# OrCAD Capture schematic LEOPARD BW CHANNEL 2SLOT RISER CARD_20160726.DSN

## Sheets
1 008 HISTORY: title: 008 HISTORY; rev: SA; company: Wiwynn Corporation; note: LEOPARD BW CHANNEL RISER CARD; note: 8F, No.90, Xintai 5th Rd., Xizhi Dist,; note: New Taipei, Taiwan
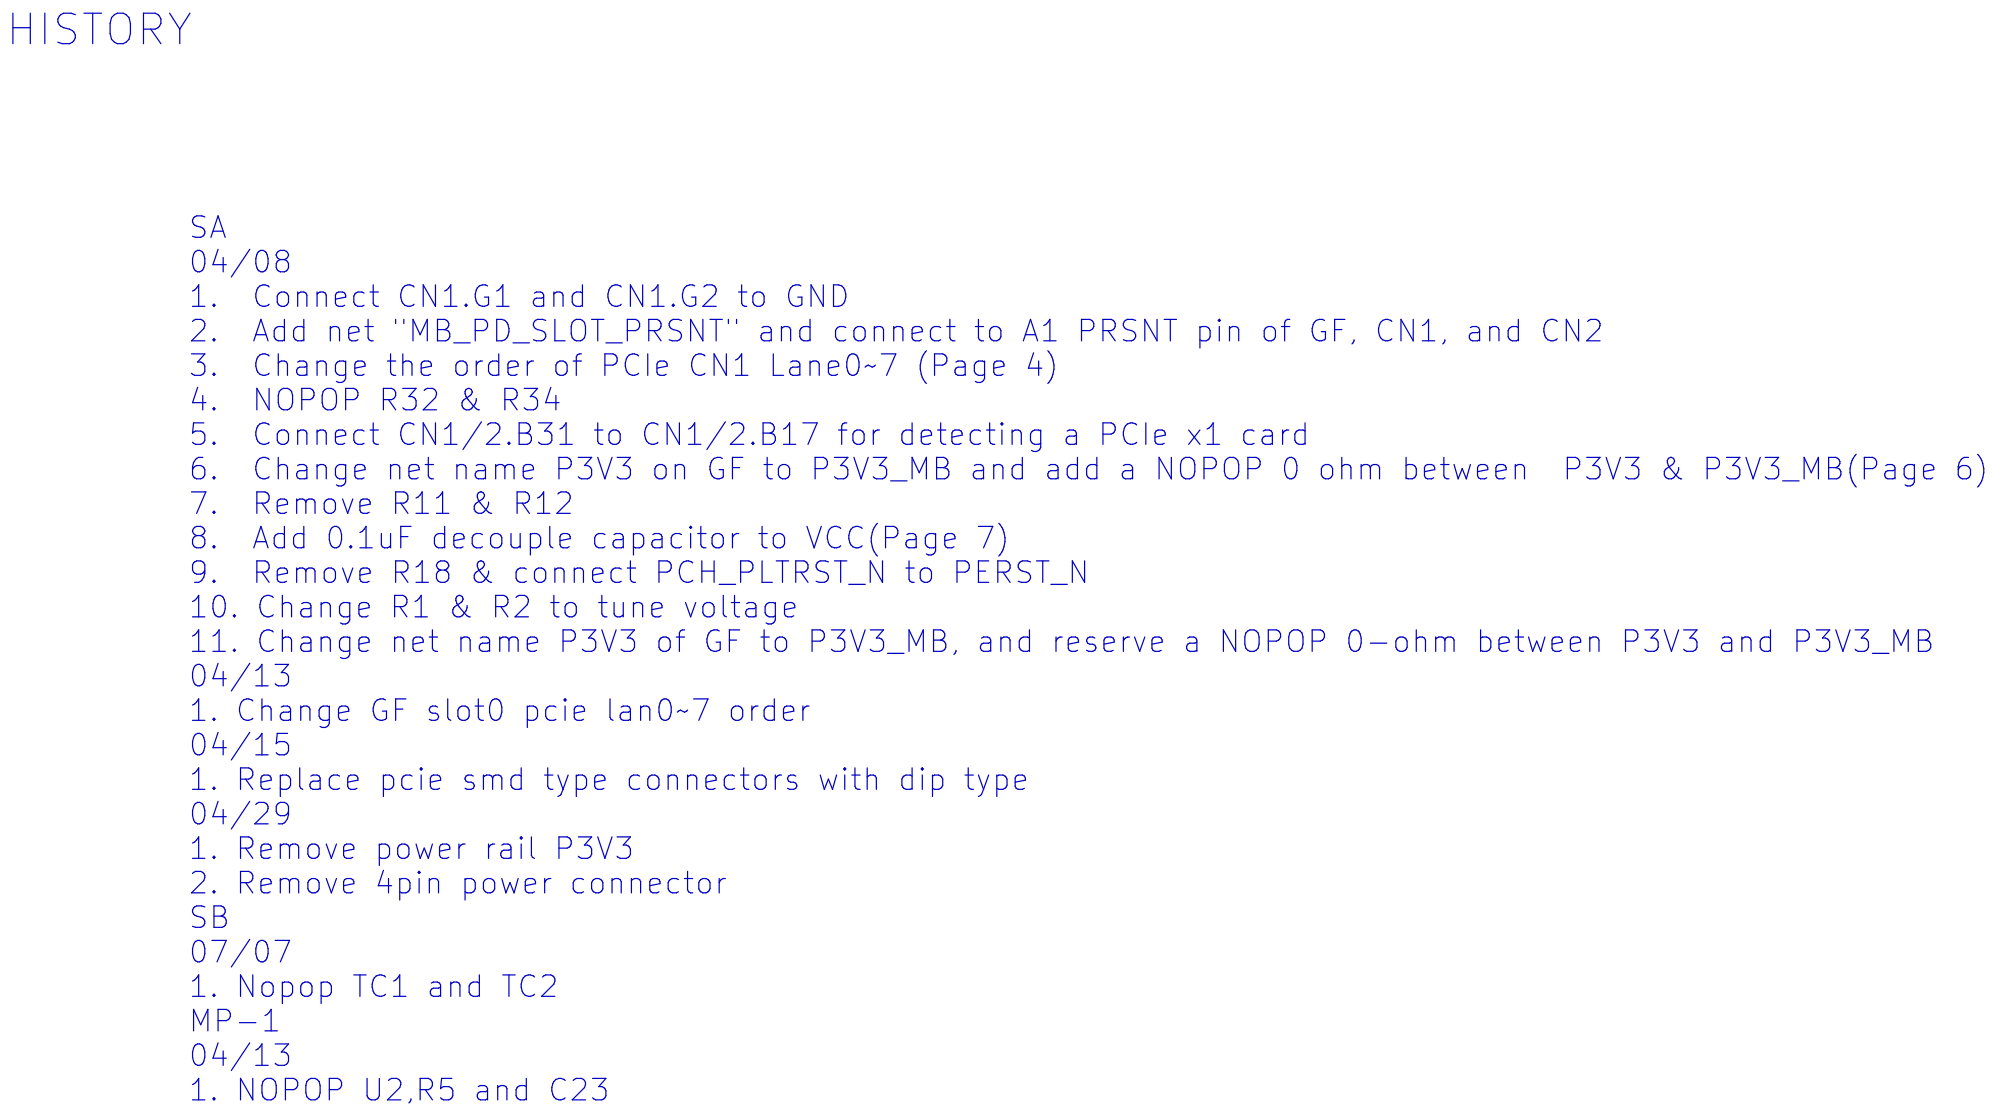
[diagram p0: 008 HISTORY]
2 007 I2C-Bus Multiplexer: size A4; title: 007 I2C-Bus Multiplexer
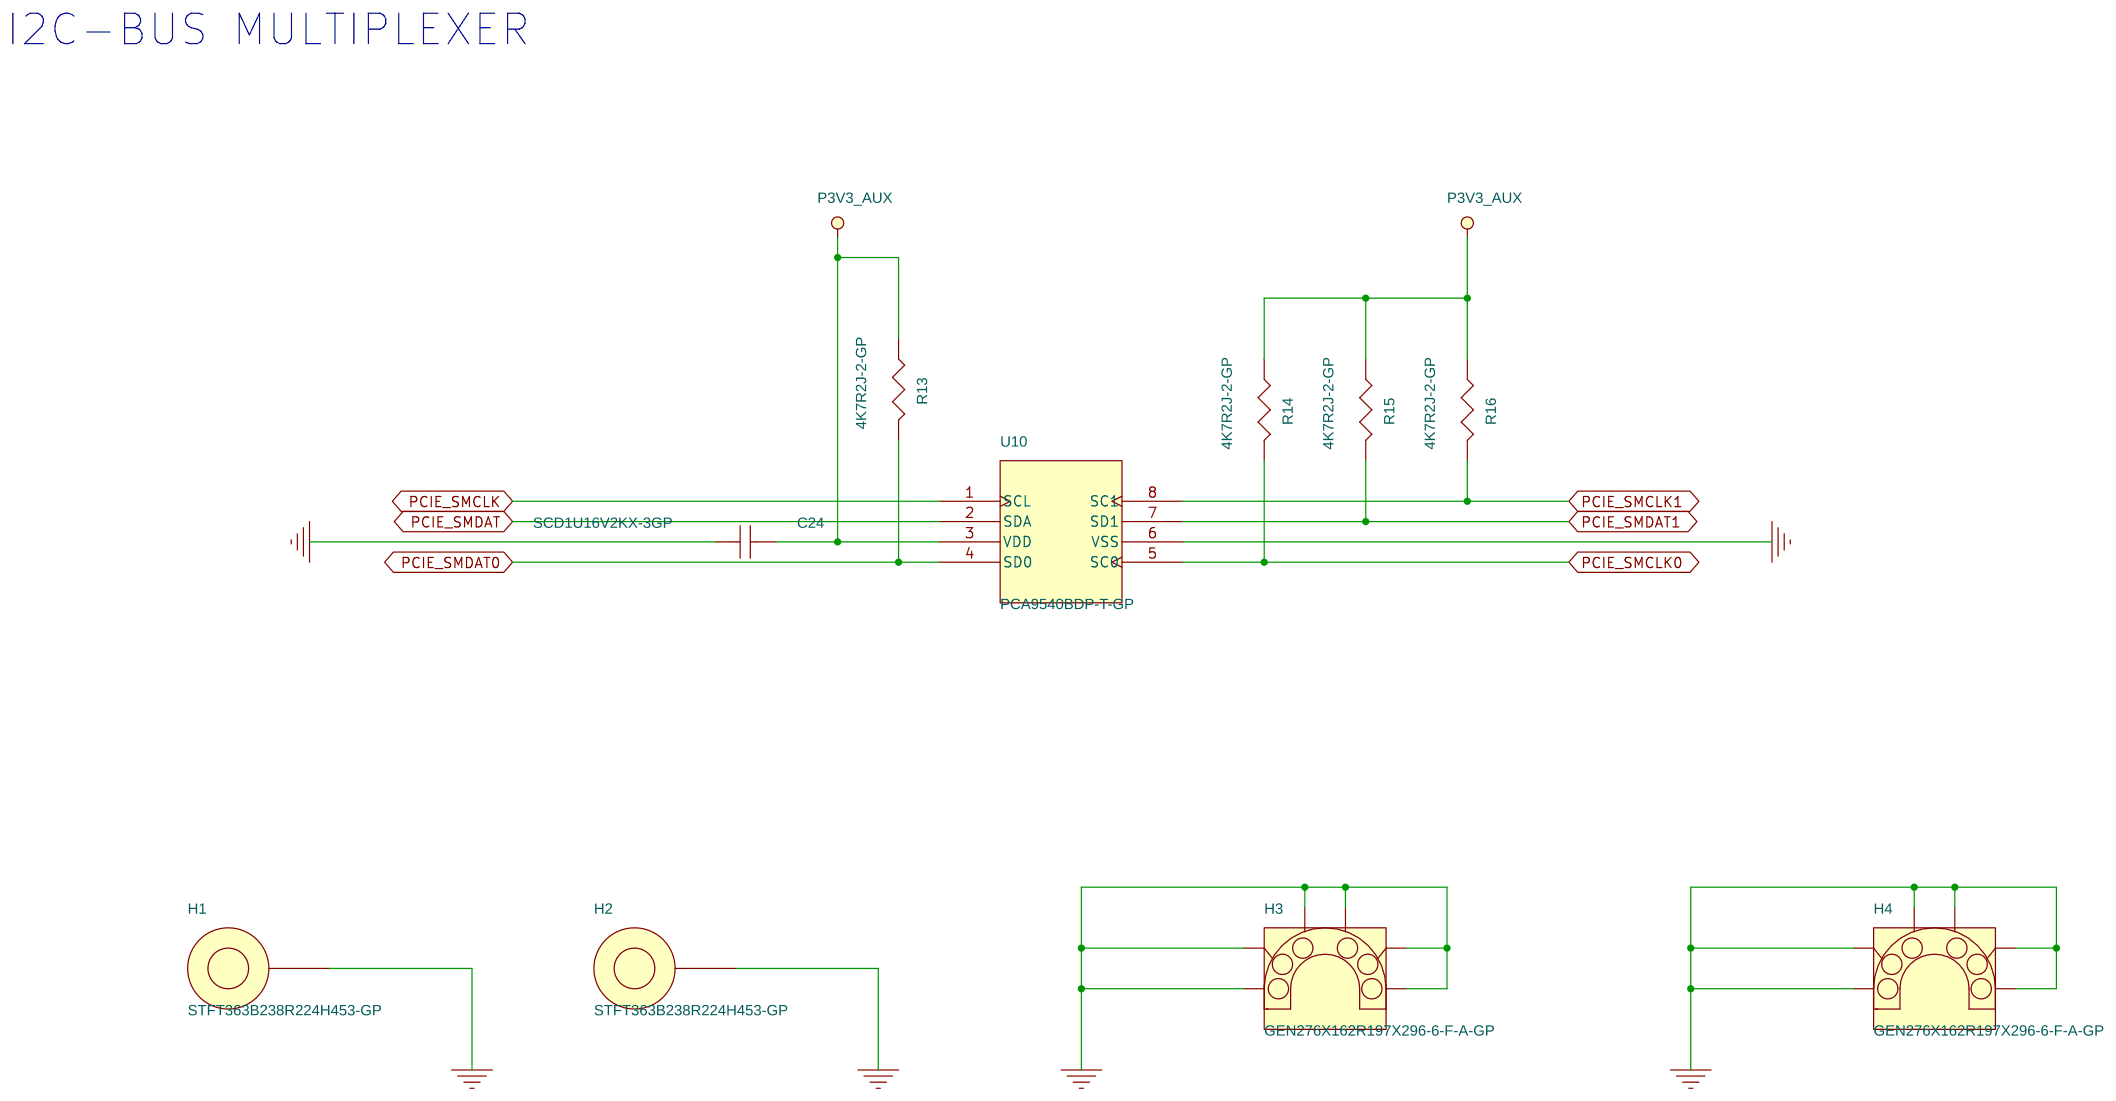
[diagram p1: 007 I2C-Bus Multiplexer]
3 006 PCIE X24 RISER GF: size A2; title: 006 PCIE X24 RISER GF
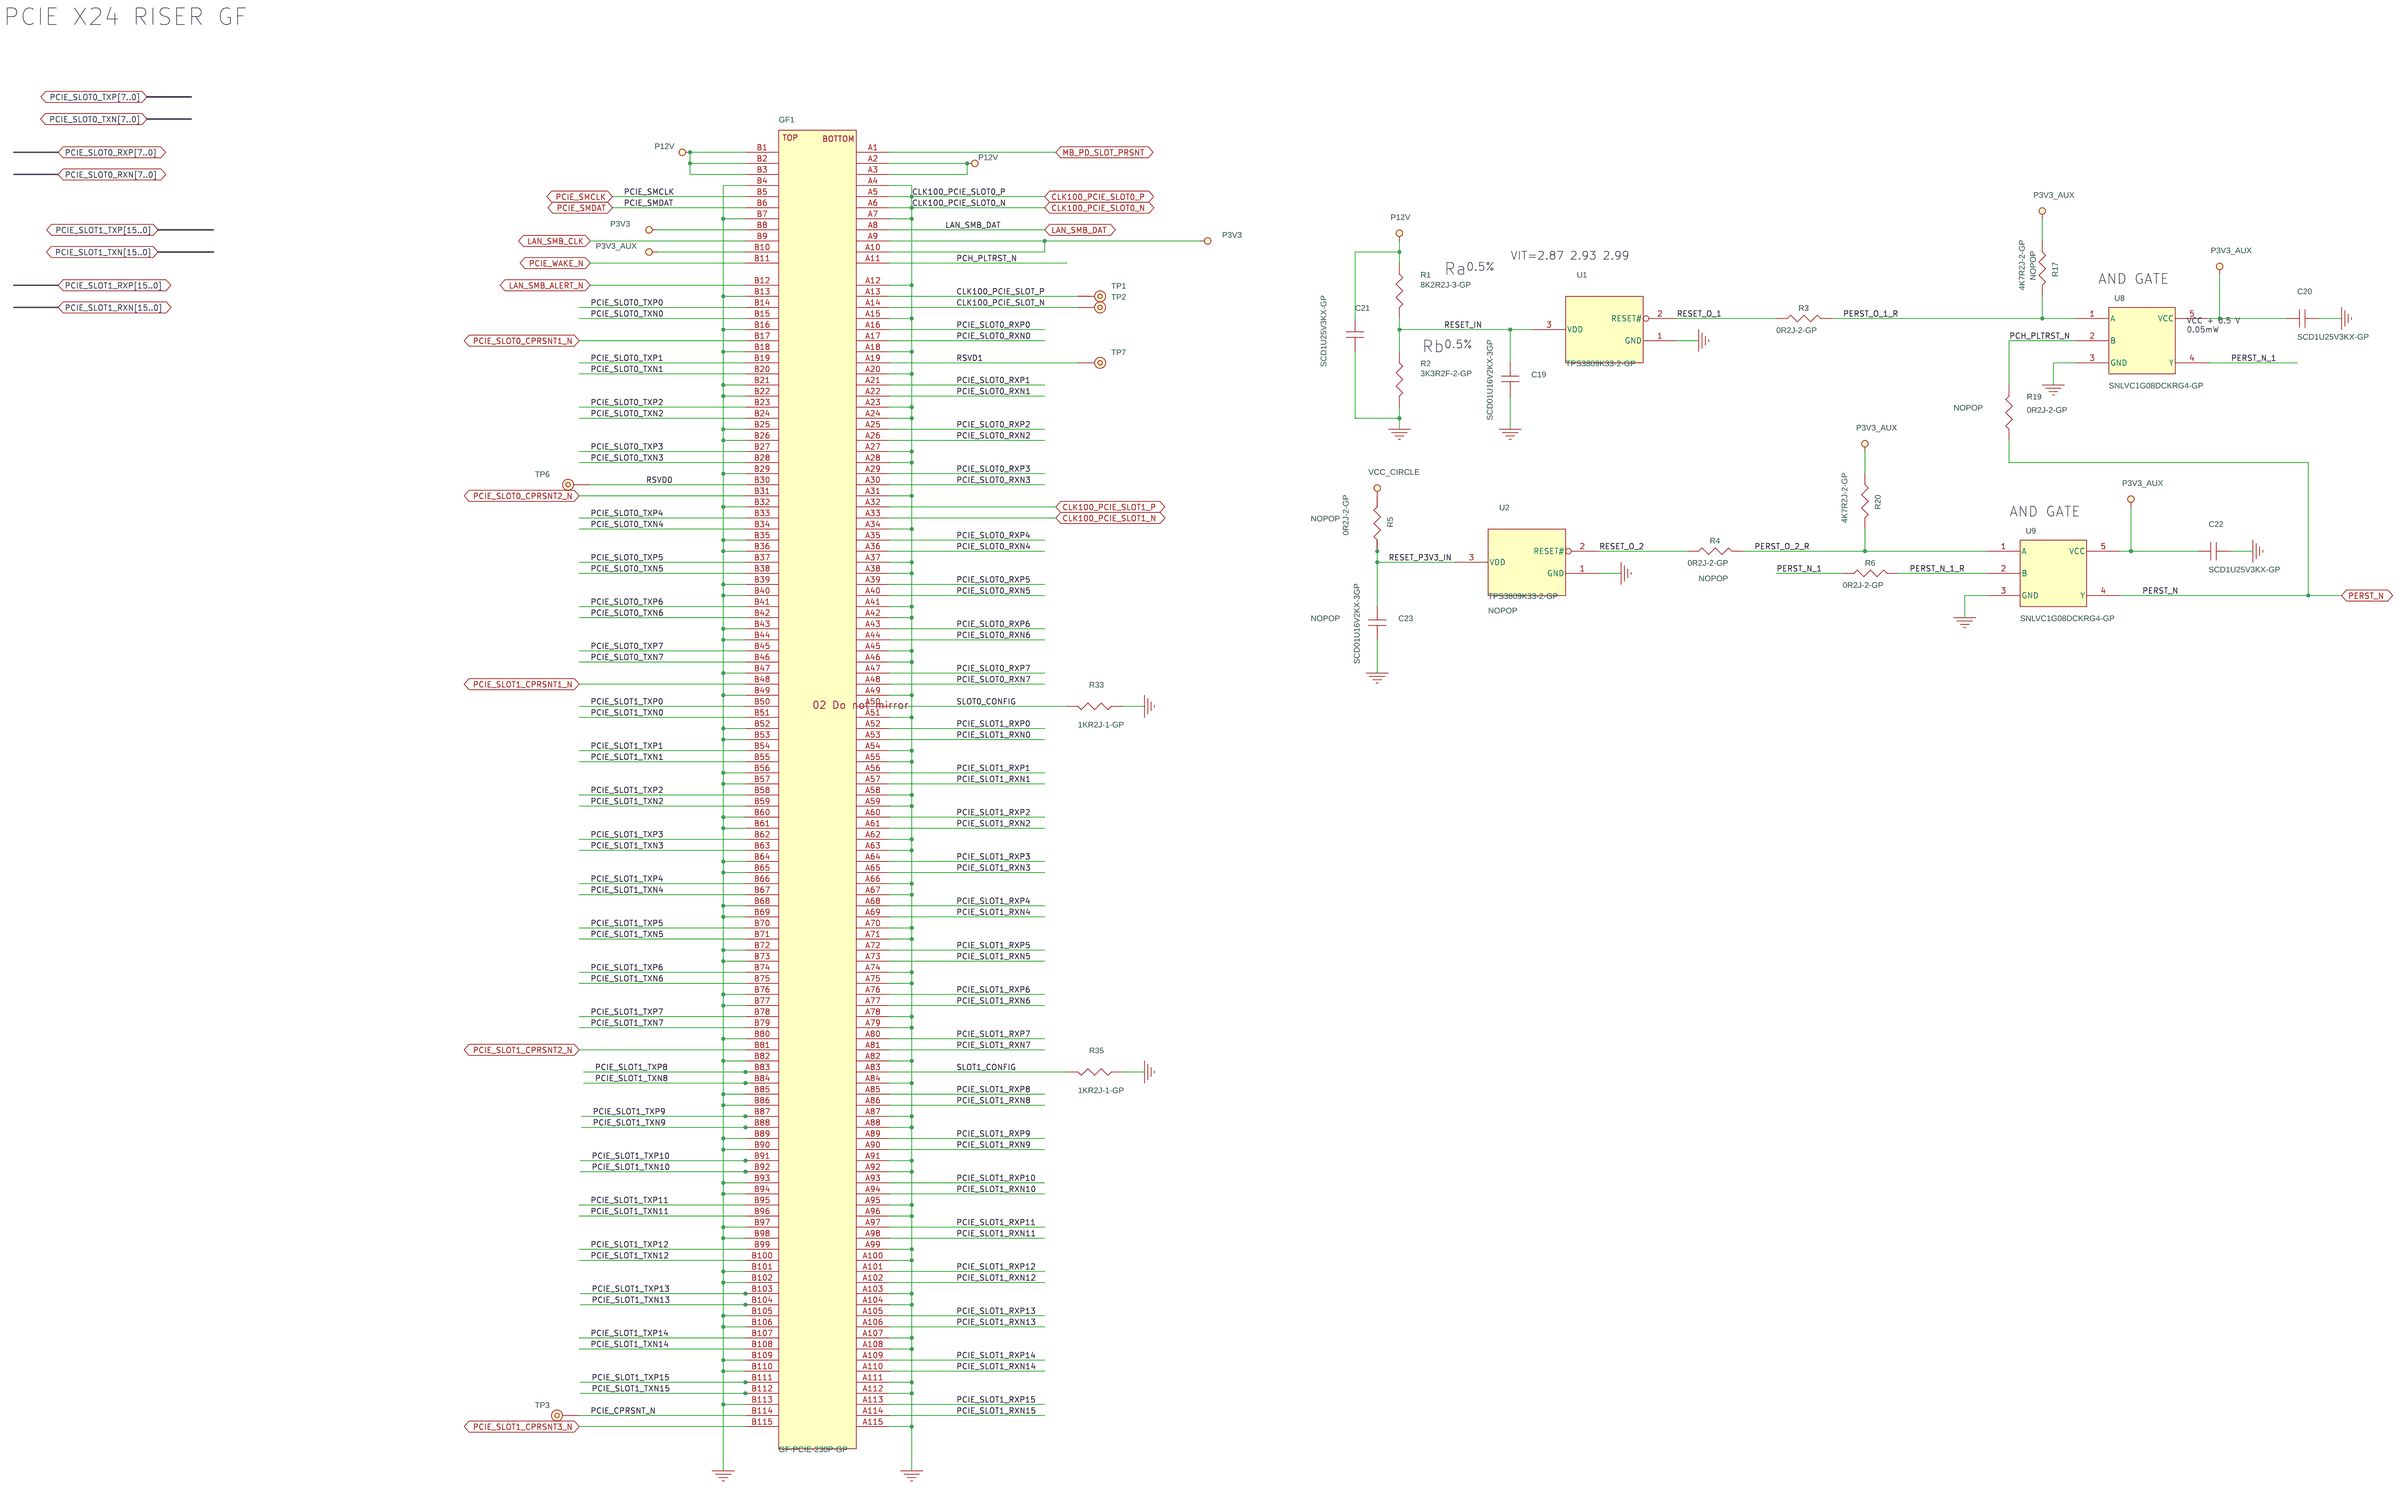
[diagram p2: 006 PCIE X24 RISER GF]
4 005 PCIE X16 RISER SLOT2: size A3; title: 005 PCIE X16 RISER SLOT3
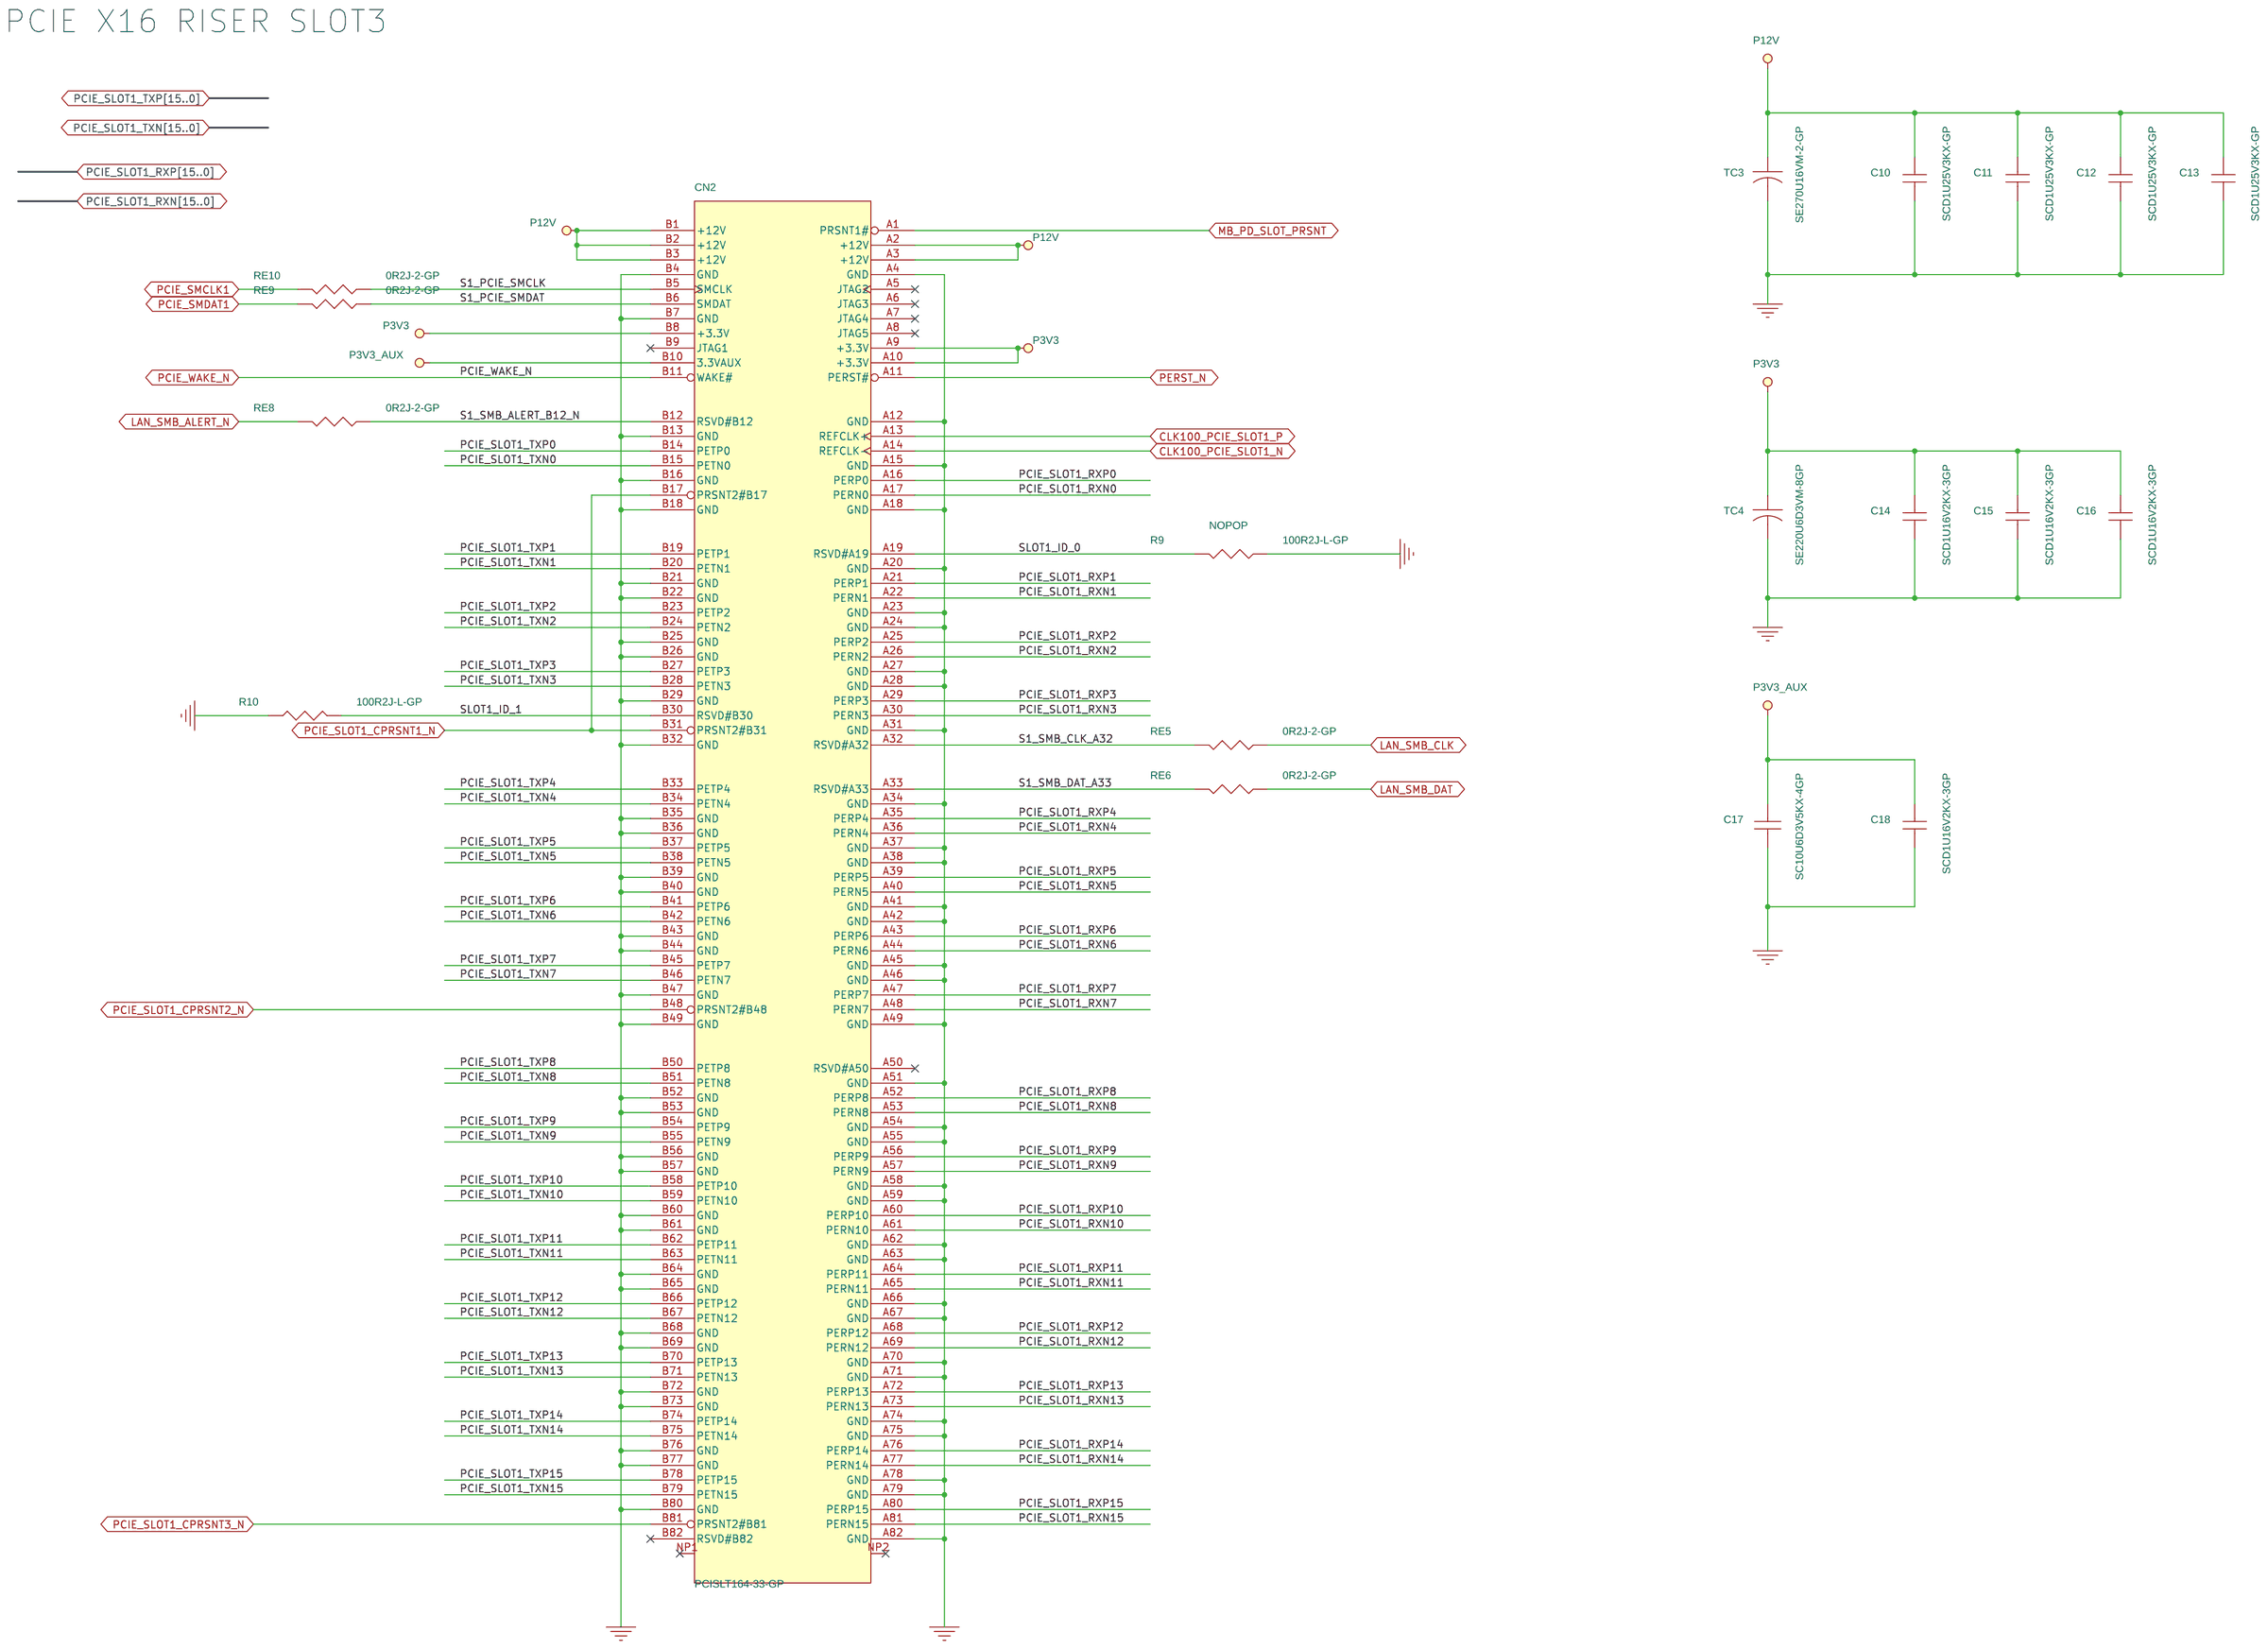
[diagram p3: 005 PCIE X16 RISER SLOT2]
5 004 PCIE X8 RISER SLOT1: size A3; title: 004 PCIE X8 RISER SLOT2
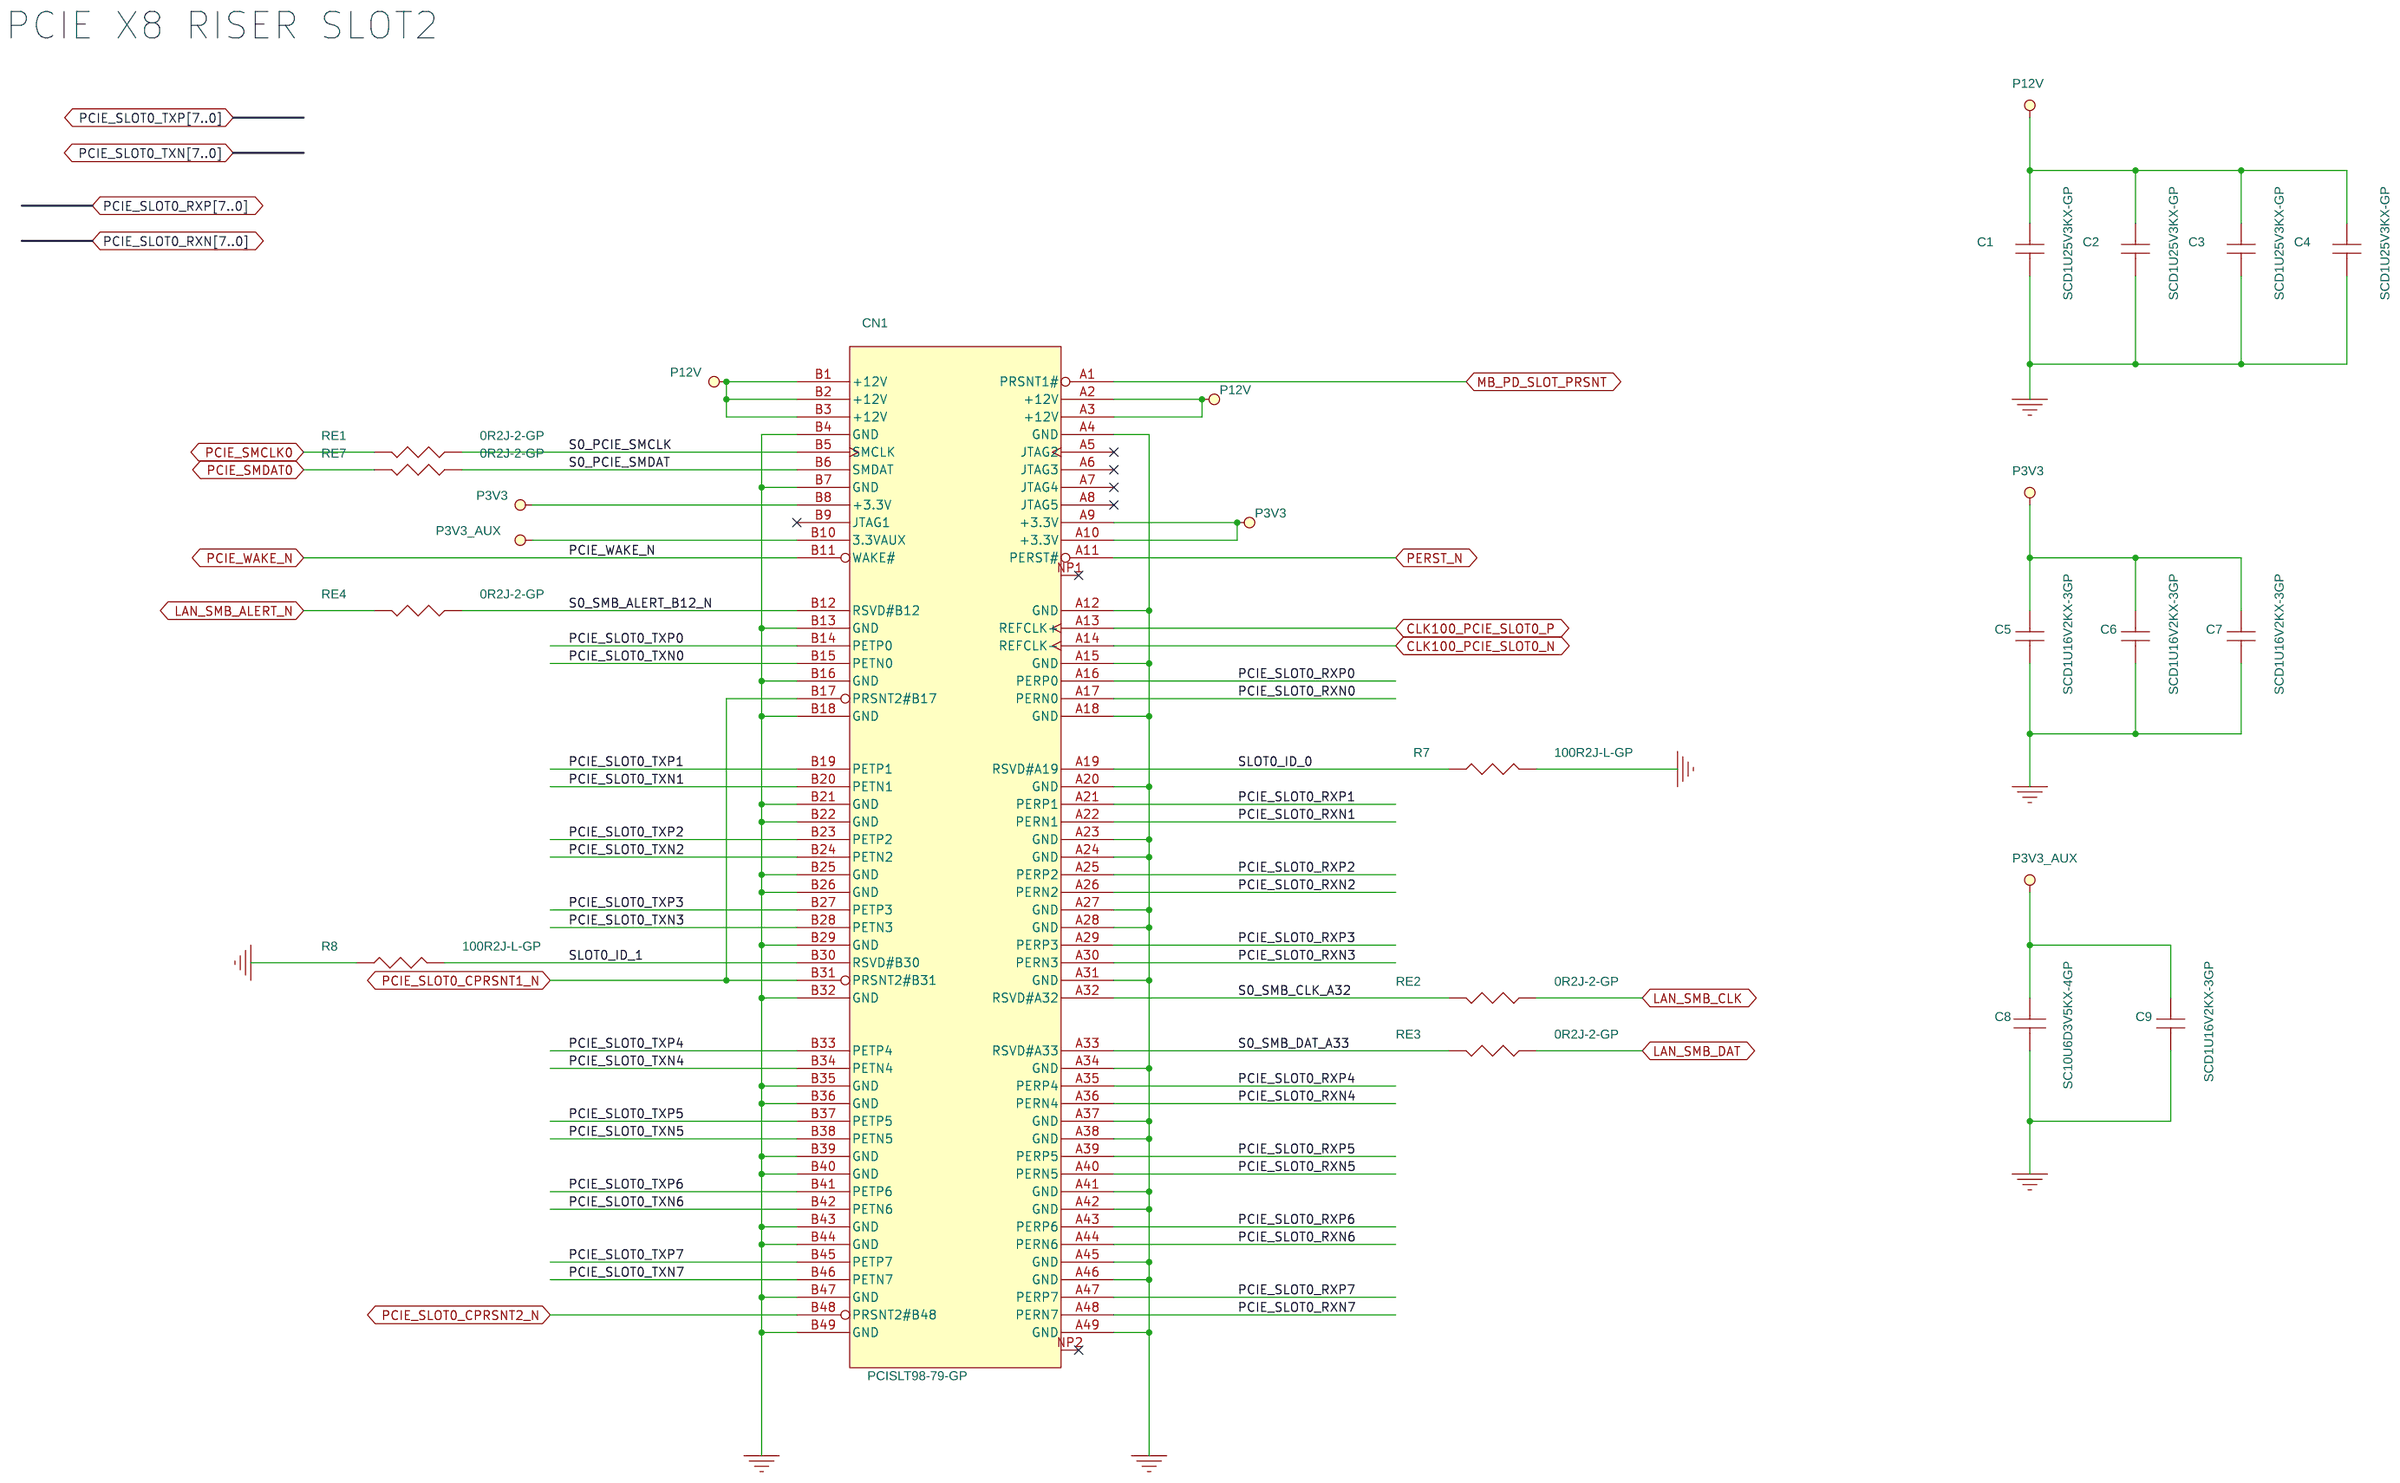
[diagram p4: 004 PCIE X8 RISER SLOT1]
6 003 STACKUP: title: 003 STACKUP
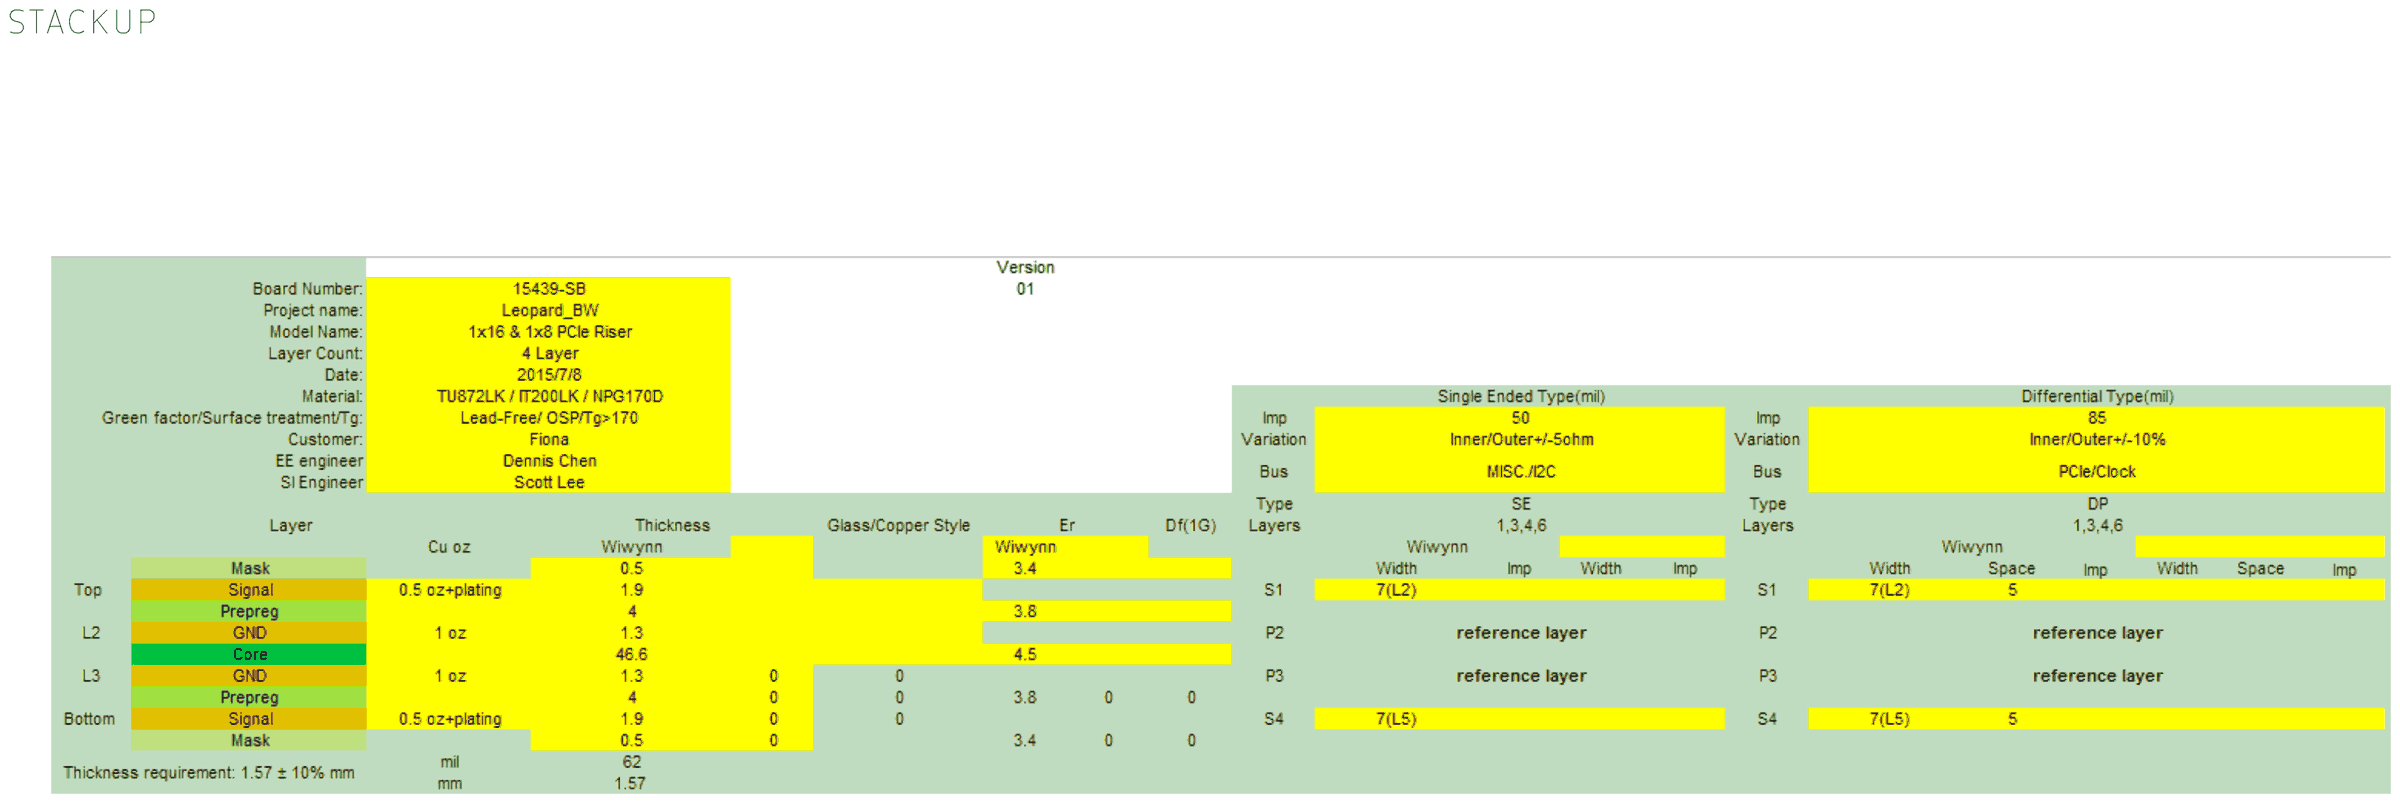
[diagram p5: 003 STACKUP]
7 002 BLOCK DIAGRAM: title: 002 BLOCK DIAGRAM
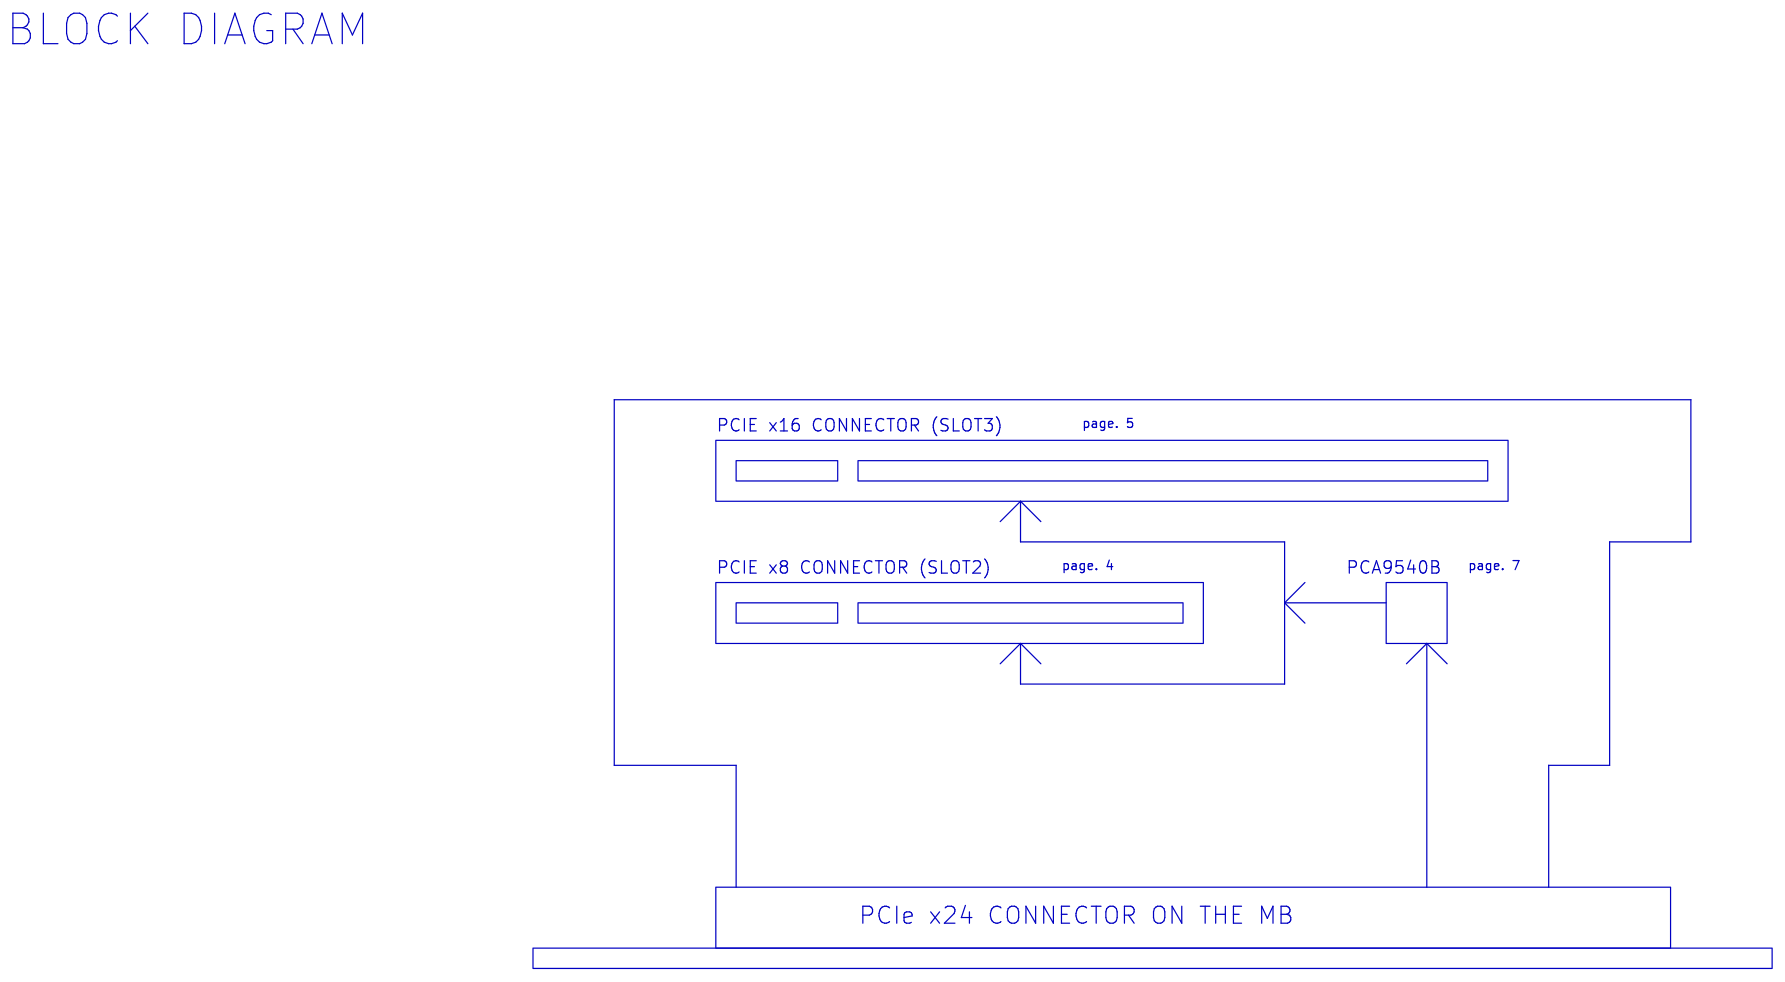
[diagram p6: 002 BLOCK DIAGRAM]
8 001 COVER PAGE: title: 001 COVER PAGE
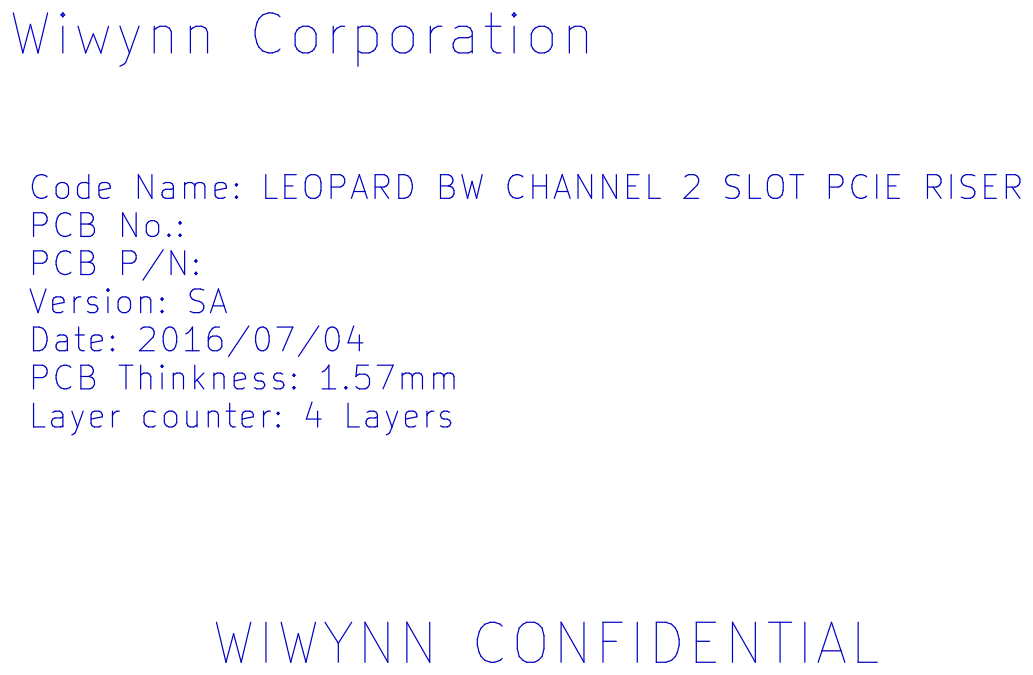
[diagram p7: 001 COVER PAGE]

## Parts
sheet 004 PCIE X8 RISER SLOT1
C1  SCD1U25V3KX-GP  [C603H36]
C2  SCD1U25V3KX-GP  [C603H36]
C3  SCD1U25V3KX-GP  [C603H36]
C4  SCD1U25V3KX-GP  [C603H36]
C5  SCD1U16V2KX-3GP  [C402H22]
C6  SCD1U16V2KX-3GP  [C402H22]
C7  SCD1U16V2KX-3GP  [C402H22]
C8  SC10U6D3V5KX-4GP  [C805H58]
C9  SCD1U16V2KX-3GP  [C402H22]
CN1  PCISLT98-79-GP  [G630H9811210TEU]
R7  100R2J-L-GP  [R402H15]
R8  100R2J-L-GP  [R402H15]
RE1  0R2J-2-GP  [R402H16]
RE2  0R2J-2-GP  [R402H16]
RE3  0R2J-2-GP  [R402H16]
RE4  0R2J-2-GP  [R402H16]
RE7  0R2J-2-GP  [R402H16]
sheet 005 PCIE X16 RISER SLOT2
C10  SCD1U25V3KX-GP  [C603H36]
C11  SCD1U25V3KX-GP  [C603H36]
C12  SCD1U25V3KX-GP  [C603H36]
C13  SCD1U25V3KX-GP  [C603H36]
C14  SCD1U16V2KX-3GP  [C402H22]
C15  SCD1U16V2KX-3GP  [C402H22]
C16  SCD1U16V2KX-3GP  [C402H22]
C17  SC10U6D3V5KX-4GP  [C805H58]
C18  SCD1U16V2KX-3GP  [C402H22]
CN2  PCISLT164-33-GP  [2EG08227-D2W-DF]
R9  100R2J-L-GP  [R402H15]
R10  100R2J-L-GP  [R402H15]
RE5  0R2J-2-GP  [R402H16]
RE6  0R2J-2-GP  [R402H16]
RE8  0R2J-2-GP  [R402H16]
RE9  0R2J-2-GP  [R402H16]
RE10  0R2J-2-GP  [R402H16]
TC3  SE270U16VM-2-GP  [SE391427H276]
TC4  SE220U6D3VM-8GP  [SE331721H237]
sheet 006 PCIE X24 RISER GF
C19  SCD01U16V2KX-3GP  [C402H22]
C20  SCD1U25V3KX-GP  [C603H36]
C21  SCD1U25V3KX-GP  [C603H36]
C22  SCD1U25V3KX-GP  [C603H36]
C23  SCD01U16V2KX-3GP  [C402H22]
GF1  GF-PCIE-230P-GP  [GF-PCIE-230P]
R1  8K2R2J-3-GP  [R402H16]
R2  3K3R2F-2-GP  [R402H16]
R3  0R2J-2-GP  [R402H16]
R4  0R2J-2-GP  [R402H16]
R5  0R2J-2-GP  [R402H16]
R6  0R2J-2-GP  [R402H16]
R17  4K7R2J-2-GP  [R402H16]
R19  0R2J-2-GP  [R402H16]
R20  4K7R2J-2-GP  [R402H16]
R33  1KR2J-1-GP  [R402H16]
R35  1KR2J-1-GP  [R402H16]
TP1  TPAD24  [TPAD24]
TP2  TPAD24  [TPAD24]
TP3  TPAD24  [TPAD24]
TP6  TPAD24  [TPAD24]
TP7  TPAD24  [TPAD24]
U1  TPS3809K33-2-GP  [SOT-23-1H58]
U2  TPS3809K33-2-GP  [SOT-23-1H58]
U8  SNLVC1G08DCKRG4-GP  [SC70-5H44]
U9  SNLVC1G08DCKRG4-GP  [SC70-5H44]
sheet 007 I2C-Bus Multiplexer
C24  SCD1U16V2KX-3GP  [C402H22]
H1  STFT363B238R224H453-GP  [STFT363B238R224H453]
H2  STFT363B238R224H453-GP  [STFT363B238R224H453]
H3  GEN276X162R197X296-6-F-A-GP  [GEN276X162R197X296-6-F-A]
H4  GEN276X162R197X296-6-F-A-GP  [GEN276X162R197X296-6-F-A]
R13  4K7R2J-2-GP  [R402H16]
R14  4K7R2J-2-GP  [R402H16]
R15  4K7R2J-2-GP  [R402H16]
R16  4K7R2J-2-GP  [R402H16]
U10  PCA9540BDP-T-GP  [SSOIC8-2H44]

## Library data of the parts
C1-C4 C10-C13 = SCD1U25V3KX-GP: CHIP CAP C 0.1U 25V K0603 X7R; CATEGORIES: CAP_1.xV; GREENDFACTOR: R2_SA;HF_SA;G_SA;; MAIN_SOURCE: M; Part Number: 78.10422.2BL; Part Type: RCL_GP; SPEC: http://wpqssvr.wistron.com.tw:7001/wpqs/servlet/COM.qpart.Attachment?PartNumber=78.10422.2BL
C5-C7 C9 C14-C16 C18 = SCD1U16V2KX-3GP: CHIP CAP C 0.1U 16V K0402 X7R; CATEGORIES: CAP_1.xV; GREENDFACTOR: R2_SA;HF_SA;G_SA;; MAIN_SOURCE: M; POP?: POP; Package Type: SMD-BCG; Part Number: 78.10421.2FL; SPEC: http://wpqssvr.wistron.com.tw:7001/wpqs/servlet/COM.qpart.Attachment?PartNumber=78.10421.2FL
C8 C17 = SC10U6D3V5KX-4GP: CHIP CAP C 10U 6.3V K0805 X7R; GREENDFACTOR: R2_SA;HF_SA;G_SA;; POP?: POP; Package Type: SMD-BCG; Part Number: 78.10620.21L; SPEC: http://wpqssvr.wistron.com.tw:7001/wpqs/servlet/COM.qpart.Attachment?PartNumber=78.10620.21L
CN1 = PCISLT98-79-GP: CONN EDGE DIP 98P G630H9811210TEU; GREENDFACTOR: R2_C;; Part Number: 020.50107.0098; Part Type: CONN-G7; SPEC: http://wpqssvr.wistron.com.tw:7001/wpqs/servlet/COM.qpart.Attachment?PartNumber=020.50107.0098
R7 R8 R10 = 100R2J-L-GP: CHIP RES 100 J 1/16W 0402 13" REEL; GREENDFACTOR: R2_SA;HF_SA;G_SA;; POP?: POP; Package Type: SMD-RG5; Part Number: 63.10134.L0L; SPEC: http://wpqssvr.wistron.com.tw:7001/wpqs/servlet/COM.qpart.Attachment?PartNumber=63.10134.L0L
RE1-RE10 = 0R2J-2-GP: CHIP RES 0 J 1/16W 0402; Category: CPLD; GREENDFACTOR: R2_SA;HF_SA;G_SA;; POP?: POP; Part Number: 63.R0034.1DL; Part Type: SMD-RG; SPEC: http://wpqssvr.wistron.com.tw:7001/wpqs/servlet/COM.qpart.Attachment?PartNumber=63.R0034.1DL
CN2 = PCISLT164-33-GP: CONN EDGE 164P ST 1-1734774-6 ,PA46/PA9T; GREENDFACTOR: R2_SA;HF_SA;; Part Number: 20.50449.164; Part Type: CONN-G6; SPEC: http://wpqssvr.wistron.com.tw:7001/wpqs/servlet/COM.qpart.Attachment?PartNumber=20.50449.164
R9 = 100R2J-L-GP: CHIP RES 100 J 1/16W 0402 13" REEL; GREENDFACTOR: R2_SA;HF_SA;G_SA;; POP?: NOPOP; Package Type: SMD-RG5; Part Number: 63.10134.L0L; SPEC: http://wpqssvr.wistron.com.tw:7001/wpqs/servlet/COM.qpart.Attachment?PartNumber=63.10134.L0L
TC3 = SE270U16VM-2-GP: CHIP CAP 270U 16V M 8.0*6.9 SVPF OS-CON; GREENDFACTOR: R2_C;; Package Type: SMD-TCG1; Part Number: 77.52771.01L; SPEC: http://wpqssvr.wistron.com.tw:7001/wpqs/servlet/COM.qpart.Attachment?PartNumber=77.52771.01L
TC4 = SE220U6D3VM-8GP: CHIP CAP EL 220U6.3V M6.3*5.9; CATEGORIES: CAP_USB; GREENDFACTOR: R2_SA;HF_SA;; MAIN_SOURCE: M; Package Type: SMD-TCG; Part Number: 79.22710.E0L; SPEC: http://wpqssvr.wistron.com.tw:7001/wpqs/servlet/COM.qpart.Attachment?PartNumber=79.22710.E0L
C19 = SCD01U16V2KX-3GP: CHIP CAP C 0.01U 16V K0402 X7R; CATEGORIES: CAP_3V/5V; GREENDFACTOR: R2_SA;HF_SA;G_SA;; MAIN_SOURCE: M; Part Number: 78.10321.2FL; Part Type: SMD-BCG; SPEC: http://wpqssvr.wistron.com.tw:7001/wpqs/servlet/COM.qpart.Attachment?PartNumber=78.10321.2FL
C20 C22 = SCD1U25V3KX-GP: CHIP CAP C 0.1U 25V K0603 X7R; CATEGORIES: CAP_1.xV; GREENDFACTOR: R2_SA;R_SA;HF_SA;G_SA;; MAIN_SOURCE: M; POP?: POP; Package Type: RCL_GP; Part Number: 78.10422.2BL; SPEC: http://wpqssvr.wistron.com.tw:7001/wpqs/servlet/COM.qpart.Attachment?PartNumber=78.10422.2BL
C21 = SCD1U25V3KX-GP: CHIP CAP C 0.1U 25V K0603 X7R; CATEGORIES: CAP_1.xV; GREENDFACTOR: R2_SA;HF_SA;G_SA;; MAIN_SOURCE: M; POP?: POP; Package Type: RCL_GP; Part Number: 78.10422.2BL; SPEC: http://wpqssvr.wistron.com.tw:7001/wpqs/servlet/COM.qpart.Attachment?PartNumber=78.10422.2BL
C23 = SCD01U16V2KX-3GP: CHIP CAP C 0.01U 16V K0402 X7R; CATEGORIES: CAP_3V/5V; GREENDFACTOR: R2_SA;HF_SA;G_SA;; MAIN_SOURCE: M; POP?: NOPOP; Part Number: 78.10321.2FL; Part Type: SMD-BCG; SPEC: http://wpqssvr.wistron.com.tw:7001/wpqs/servlet/COM.qpart.Attachment?PartNumber=78.10321.2FL
GF1 = GF-PCIE-230P-GP: PCIE GOLD FINGURE 230P; GREENDFACTOR: R2_C;; Package Type: CONN-G7; Part Number: ZZ.GF001.711; SPEC: http://wpqssvr.wistron.com.tw:7001/wpqs/servlet/COM.qpart.Attachment?PartNumber=ZZ.GF001.711
R1 = 8K2R2J-3-GP: CHIP RES 8.2K J 1/16W 0402; GREENDFACTOR: R2_SA;HF_SA;G_SA;; Part Number: 63.82234.1DL; Part Type: SMD-RG; SPEC: http://wpqssvr.wistron.com.tw:7001/wpqs/servlet/COM.qpart.Attachment?PartNumber=63.82234.1DL
R2 = 3K3R2F-2-GP: CHIP RES 3.3K F 1/16W 0402; GREENDFACTOR: R2_SA;HF_SA;G_SA;; Part Number: 64.33015.6DL; Part Type: SMD-RG; SPEC: http://wpqssvr.wistron.com.tw:7001/wpqs/servlet/COM.qpart.Attachment?PartNumber=64.33015.6DL
R3 = 0R2J-2-GP: CHIP RES 0 J 1/16W 0402; Category: HOTPLUG_CONTROL; GREENDFACTOR: R2_SA;HF_SA;G_SA;; POP?: POP; Package Type: SMD-RG; Part Number: 63.R0034.1DL; Part Type: SMD-RG; SPEC: http://wpqssvr.wistron.com.tw:7001/wpqs/servlet/COM.qpart.Attachment?PartNumber=63.R0034.1DL
R4 R5 R19 = 0R2J-2-GP: CHIP RES 0 J 1/16W 0402; Category: HOTPLUG_CONTROL; GREENDFACTOR: R2_SA;HF_SA;G_SA;; POP?: NOPOP; Package Type: SMD-RG; Part Number: 63.R0034.1DL; Part Type: SMD-RG; SPEC: http://wpqssvr.wistron.com.tw:7001/wpqs/servlet/COM.qpart.Attachment?PartNumber=63.R0034.1DL
R6 = 0R2J-2-GP: CHIP RES 0 J 1/16W 0402; Category: HOTPLUG_CONTROL; GREENDFACTOR: R2_SA;HF_SA;G_SA;; Package Type: SMD-RG; Part Number: 63.R0034.1DL; Part Type: SMD-RG; SPEC: http://wpqssvr.wistron.com.tw:7001/wpqs/servlet/COM.qpart.Attachment?PartNumber=63.R0034.1DL
R17 = 4K7R2J-2-GP: CHIP RES 4.7K J 1/16W 0402; GREENDFACTOR: R2_SA;HF_SA;G_SA;; POP?: NOPOP; Part Number: 63.47234.1DL; Part Type: SMD-RG; SPEC: http://wpqssvr.wistron.com.tw:7001/wpqs/servlet/COM.qpart.Attachment?PartNumber=63.47234.1DL
R20 = 4K7R2J-2-GP: CHIP RES 4.7K J 1/16W 0402; GREENDFACTOR: R2_SA;HF_SA;G_SA;; POP?: POP; Part Number: 63.47234.1DL; Part Type: SMD-RG; SPEC: http://wpqssvr.wistron.com.tw:7001/wpqs/servlet/COM.qpart.Attachment?PartNumber=63.47234.1DL
R33 = 1KR2J-1-GP: CHIP RES 1K J 1/16W 0402; Belong: POP; Category: PCH; GREENDFACTOR: R2_SA;HF_SA;G_SA;; POP?: POP; Package Type: SMD-RG; Part Number: 63.10234.1DL; Part Type: SMD-RG; SPEC: http://wpqssvr.wistron.com.tw:7001/wpqs/servlet/COM.qpart.Attachment?PartNumber=63.10234.1DL
R35 = 1KR2J-1-GP: CHIP RES 1K J 1/16W 0402; Belong: POP; Category: PCH; GREENDFACTOR: R2_SA;HF_SA;G_SA;; Package Type: SMD-RG; Part Number: 63.10234.1DL; Part Type: SMD-RG; SPEC: http://wpqssvr.wistron.com.tw:7001/wpqs/servlet/COM.qpart.Attachment?PartNumber=63.10234.1DL
TP1-TP3 TP6 TP7 = TPAD24: 24 MILS TEST PAD; GREENDFACTOR: Regular;; Package Type: DISCRET2; Part Number: ZZ.PAD24.001; SPEC: http://wpqssvr.wistron.com.tw:7001/wpqs/servlet/COM.qpart.Attachment?PartNumber=ZZ.PAD24.001
U1 = TPS3809K33-2-GP: IC RESET TPS3809K33DBVT SOT-23; GREENDFACTOR: R2_SA;; POP?: POP; Package Type: DISCRET-G; Part Number: 74.03809.07B; SPEC: http://wpqssvr.wistron.com.tw:7001/wpqs/servlet/COM.qpart.Attachment?PartNumber=74.03809.07B
U2 = TPS3809K33-2-GP: IC RESET TPS3809K33DBVT SOT-23; GREENDFACTOR: R2_SA;; POP?: NOPOP; Package Type: DISCRET-G; Part Number: 74.03809.07B; SPEC: http://wpqssvr.wistron.com.tw:7001/wpqs/servlet/COM.qpart.Attachment?PartNumber=74.03809.07B
U8 U9 = SNLVC1G08DCKRG4-GP: IC CMOS SN74LVC1G08DCKRG4 DCK; GREENDFACTOR: R_SA;G_SA;; POP?: POP; Package Type: TTL-G; Part Number: 73.01G08.DHG; SPEC: http://wpqssvr.wistron.com.tw:7001/wpqs/servlet/COM.qpart.Attachment?PartNumber=73.01G08.DHG
C24 = SCD1U16V2KX-3GP: CHIP CAP C 0.1U 16V K0402 X7R; CATEGORIES: CAP_1.xV; GREENDFACTOR: R2_SA;HF_SA;G_SA;; MAIN_SOURCE: M; Part Number: 78.10421.2FL; Part Type: SMD-BCG; SPEC: http://wpqssvr.wistron.com.tw:7001/wpqs/servlet/COM.qpart.Attachment?PartNumber=78.10421.2FL
H1 H2 = STFT363B238R224H453-GP: THUMB SCREW SMT M3X0.5 L4.6; GREENDFACTOR: R2_C;; Part Number: 086.2AT24.04R6; Part Type: DISCRET-GC1; SPEC: http://wpqssvr.wistron.com.tw:7001/wpqs/servlet/COM.qpart.Attachment?PartNumber=086.2AT24.04R6
H3 H4 = GEN276X162R197X296-6-F-A-GP: SCREW HOLE TYPE A; GREENDFACTOR: R2_C;; Part Number: ZZ.SCREW.511; Part Type: DISCRET-G8; SPEC: http://wpqssvr.wistron.com.tw:7001/wpqs/servlet/COM.qpart.Attachment?PartNumber=ZZ.SCREW.511
R13-R16 = 4K7R2J-2-GP: CHIP RES 4.7K J 1/16W 0402; GREENDFACTOR: R2_SA;HF_SA;G_SA;; Part Number: 63.47234.1DL; Part Type: SMD-RG; SPEC: http://wpqssvr.wistron.com.tw:7001/wpqs/servlet/COM.qpart.Attachment?PartNumber=63.47234.1DL
U10 = PCA9540BDP-T-GP: IC CTRL PCA9540BDP-T TSSOP 8P; GREENDFACTOR: R_C;; Part Number: 71.09540.A0W; Part Type: DISCRET-G3; SPEC: http://wpqssvr.wistron.com.tw:7001/wpqs/servlet/COM.qpart.Attachment?PartNumber=71.09540.A0W

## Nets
GND: C1.2 C2.2 C3.2 C4.2 C5.2 C6.2 C7.2 C8.2 C9.2 C10.2 C11.2 C12.2 C13.2 C14.2 C15.2 C16.2 C17.2 C18.2 C19.2 C20.2 C21.2 C22.2 C23.2 C24.1 CN1.A4(GND) CN1.A12(GND) CN1.A15(GND) CN1.A18(GND) CN1.A20(GND) CN1.A23(GND) CN1.A24(GND) CN1.A27(GND) CN1.A28(GND) CN1.A31(GND) CN1.A34(GND) CN1.A37(GND) CN1.A38(GND) CN1.A41(GND) CN1.A42(GND) CN1.A45(GND) CN1.A46(GND) CN1.A49(GND) CN1.B4(GND) CN1.B7(GND) CN1.B13(GND) CN1.B16(GND) CN1.B18(GND) CN1.B21(GND) CN1.B22(GND) CN1.B25(GND) CN1.B26(GND) CN1.B29(GND) CN1.B32(GND) CN1.B35(GND) CN1.B36(GND) CN1.B39(GND) CN1.B40(GND) CN1.B43(GND) CN1.B44(GND) CN1.B47(GND) CN1.B49(GND) CN2.A4(GND) CN2.A12(GND) CN2.A15(GND) CN2.A18(GND) CN2.A20(GND) CN2.A23(GND) CN2.A24(GND) CN2.A27(GND) CN2.A28(GND) CN2.A31(GND) CN2.A34(GND) CN2.A37(GND) CN2.A38(GND) CN2.A41(GND) CN2.A42(GND) CN2.A45(GND) CN2.A46(GND) CN2.A49(GND) CN2.A51(GND) CN2.A54(GND) CN2.A55(GND) CN2.A58(GND) CN2.A59(GND) CN2.A62(GND) CN2.A63(GND) CN2.A66(GND) CN2.A67(GND) CN2.A70(GND) CN2.A71(GND) CN2.A74(GND) CN2.A75(GND) CN2.A78(GND) CN2.A79(GND) CN2.A82(GND) CN2.B4(GND) CN2.B7(GND) CN2.B13(GND) CN2.B16(GND) CN2.B18(GND) CN2.B21(GND) CN2.B22(GND) CN2.B25(GND) CN2.B26(GND) CN2.B29(GND) CN2.B32(GND) CN2.B35(GND) CN2.B36(GND) CN2.B39(GND) CN2.B40(GND) CN2.B43(GND) CN2.B44(GND) CN2.B47(GND) CN2.B49(GND) CN2.B52(GND) CN2.B53(GND) CN2.B56(GND) CN2.B57(GND) CN2.B60(GND) CN2.B61(GND) CN2.B64(GND) CN2.B65(GND) CN2.B68(GND) CN2.B69(GND) CN2.B72(GND) CN2.B73(GND) CN2.B76(GND) CN2.B77(GND) CN2.B80(GND) GF1.A4 GF1.A7 GF1.A12 GF1.A15 GF1.A18 GF1.A20 GF1.A23 GF1.A24 GF1.A27 GF1.A28 GF1.A31 GF1.A34 GF1.A37 GF1.A38 GF1.A41 GF1.A42 GF1.A45 GF1.A46 GF1.A49 GF1.A51 GF1.A54 GF1.A55 GF1.A58 GF1.A59 GF1.A62 GF1.A63 GF1.A66 GF1.A67 GF1.A70 GF1.A71 GF1.A74 GF1.A75 GF1.A78 GF1.A79 GF1.A82 GF1.A84 GF1.A87 GF1.A88 GF1.A91 GF1.A92 GF1.A95 GF1.A96 GF1.A99 GF1.A100 GF1.A103 GF1.A104 GF1.A107 GF1.A108 GF1.A111 GF1.A112 GF1.A115 GF1.B4 GF1.B7 GF1.B13 GF1.B16 GF1.B18 GF1.B21 GF1.B22 GF1.B25 GF1.B26 GF1.B29 GF1.B32 GF1.B35 GF1.B36 GF1.B39 GF1.B40 GF1.B43 GF1.B44 GF1.B47 GF1.B49 GF1.B52 GF1.B53 GF1.B56 GF1.B57 GF1.B60 GF1.B61 GF1.B64 GF1.B65 GF1.B68 GF1.B69 GF1.B72 GF1.B73 GF1.B76 GF1.B77 GF1.B80 GF1.B82 GF1.B85 GF1.B86 GF1.B89 GF1.B90 GF1.B93 GF1.B94 GF1.B97 GF1.B98 GF1.B101 GF1.B102 GF1.B105 GF1.B106 GF1.B109 GF1.B110 GF1.B113 H1.1 H2.1 H3.1 H3.2 H3.3 H3.4 H3.5 H3.6 H4.1 H4.2 H4.3 H4.4 H4.5 H4.6 R2.2 R7.2 R8.1 R9.1 R10.1 R33.2 R35.2 TC3.2 TC4.2 U1.1(GND) U2.1(GND) U8.3(GND) U9.3(GND) U10.6(VSS)
P3V3: C5.1 C6.1 C7.1 C14.1 C15.1 C16.1 CN1.A9(+3.3V) CN1.A10(+3.3V) CN1.B8(+3.3V) CN2.A9(+3.3V) CN2.A10(+3.3V) CN2.B8(+3.3V) GF1.A9 GF1.A10 GF1.B8 R5.2 TC4.1
P3V3_AUX: C8.1 C9.1 C17.1 C18.1 C20.1 C22.1 C24.2 CN1.B10(3.3VAUX) CN2.B10(3.3VAUX) GF1.B10 R13.1 R14.1 R15.1 R16.1 R17.1 R20.1 U8.5(VCC) U9.5(VCC) U10.3(VDD)
P12V: C1.1 C2.1 C3.1 C4.1 C10.1 C11.1 C12.1 C13.1 C21.1 CN1.A2(+12V) CN1.A3(+12V) CN1.B1(+12V) CN1.B2(+12V) CN1.B3(+12V) CN2.A2(+12V) CN2.A3(+12V) CN2.B1(+12V) CN2.B2(+12V) CN2.B3(+12V) GF1.A2 GF1.A3 GF1.B1 GF1.B2 GF1.B3 R1.1 TC3.1
CLK100_PCIE_SLOT0_N: CN1.A14(REFCLK-) GF1.A6
CLK100_PCIE_SLOT0_P: CN1.A13(REFCLK+) GF1.A5
CLK100_PCIE_SLOT1_N: CN2.A14(REFCLK-) GF1.A33
CLK100_PCIE_SLOT1_P: CN2.A13(REFCLK+) GF1.A32
CLK100_PCIE_SLOT_N: GF1.A14 TP2.1
CLK100_PCIE_SLOT_P: GF1.A13 TP1.1
LAN_SMB_ALERT_N: GF1.B12 RE4.2 RE8.2
LAN_SMB_CLK: GF1.B9 RE2.1 RE5.1
LAN_SMB_DAT: GF1.A8 RE3.1 RE6.1
MB_PD_SLOT_PRSNT: CN1.A1(PRSNT1#) CN2.A1(PRSNT1#) GF1.A1
PCH_PLTRST_N: GF1.A11 R19.2 U8.2(B)
PCIE_CPRSNT_N: GF1.B114 TP3.1
PCIE_SLOT0_CPRSNT1_N: CN1.B17(PRSNT2#B17) CN1.B31(PRSNT2#B31) GF1.B17
PCIE_SLOT0_CPRSNT2_N: CN1.B48(PRSNT2#B48) GF1.B31
PCIE_SLOT0_RXN0: CN1.A17(PERN0) GF1.A17
PCIE_SLOT0_RXN1: CN1.A22(PERN1) GF1.A22
PCIE_SLOT0_RXN2: CN1.A26(PERN2) GF1.A26
PCIE_SLOT0_RXN3: CN1.A30(PERN3) GF1.A30
PCIE_SLOT0_RXN4: CN1.A36(PERN4) GF1.A36
PCIE_SLOT0_RXN5: CN1.A40(PERN5) GF1.A40
PCIE_SLOT0_RXN6: CN1.A44(PERN6) GF1.A44
PCIE_SLOT0_RXN7: CN1.A48(PERN7) GF1.A48
PCIE_SLOT0_RXP0: CN1.A16(PERP0) GF1.A16
PCIE_SLOT0_RXP1: CN1.A21(PERP1) GF1.A21
PCIE_SLOT0_RXP2: CN1.A25(PERP2) GF1.A25
PCIE_SLOT0_RXP3: CN1.A29(PERP3) GF1.A29
PCIE_SLOT0_RXP4: CN1.A35(PERP4) GF1.A35
PCIE_SLOT0_RXP5: CN1.A39(PERP5) GF1.A39
PCIE_SLOT0_RXP6: CN1.A43(PERP6) GF1.A43
PCIE_SLOT0_RXP7: CN1.A47(PERP7) GF1.A47
PCIE_SLOT0_TXN0: CN1.B15(PETN0) GF1.B15
PCIE_SLOT0_TXN1: CN1.B20(PETN1) GF1.B20
PCIE_SLOT0_TXN2: CN1.B24(PETN2) GF1.B24
PCIE_SLOT0_TXN3: CN1.B28(PETN3) GF1.B28
PCIE_SLOT0_TXN4: CN1.B34(PETN4) GF1.B34
PCIE_SLOT0_TXN5: CN1.B38(PETN5) GF1.B38
PCIE_SLOT0_TXN6: CN1.B42(PETN6) GF1.B42
PCIE_SLOT0_TXN7: CN1.B46(PETN7) GF1.B46
PCIE_SLOT0_TXP0: CN1.B14(PETP0) GF1.B14
PCIE_SLOT0_TXP1: CN1.B19(PETP1) GF1.B19
PCIE_SLOT0_TXP2: CN1.B23(PETP2) GF1.B23
PCIE_SLOT0_TXP3: CN1.B27(PETP3) GF1.B27
PCIE_SLOT0_TXP4: CN1.B33(PETP4) GF1.B33
PCIE_SLOT0_TXP5: CN1.B37(PETP5) GF1.B37
PCIE_SLOT0_TXP6: CN1.B41(PETP6) GF1.B41
PCIE_SLOT0_TXP7: CN1.B45(PETP7) GF1.B45
PCIE_SLOT1_CPRSNT1_N: CN2.B17(PRSNT2#B17) CN2.B31(PRSNT2#B31) GF1.B48
PCIE_SLOT1_CPRSNT2_N: CN2.B48(PRSNT2#B48) GF1.B81
PCIE_SLOT1_CPRSNT3_N: CN2.B81(PRSNT2#B81) GF1.B115
PCIE_SLOT1_RXN0: CN2.A17(PERN0) GF1.A53
PCIE_SLOT1_RXN1: CN2.A22(PERN1) GF1.A57
PCIE_SLOT1_RXN2: CN2.A26(PERN2) GF1.A61
PCIE_SLOT1_RXN3: CN2.A30(PERN3) GF1.A65
PCIE_SLOT1_RXN4: CN2.A36(PERN4) GF1.A69
PCIE_SLOT1_RXN5: CN2.A40(PERN5) GF1.A73
PCIE_SLOT1_RXN6: CN2.A44(PERN6) GF1.A77
PCIE_SLOT1_RXN7: CN2.A48(PERN7) GF1.A81
PCIE_SLOT1_RXN8: CN2.A53(PERN8) GF1.A86
PCIE_SLOT1_RXN9: CN2.A57(PERN9) GF1.A90
PCIE_SLOT1_RXN10: CN2.A61(PERN10) GF1.A94
PCIE_SLOT1_RXN11: CN2.A65(PERN11) GF1.A98
PCIE_SLOT1_RXN12: CN2.A69(PERN12) GF1.A102
PCIE_SLOT1_RXN13: CN2.A73(PERN13) GF1.A106
PCIE_SLOT1_RXN14: CN2.A77(PERN14) GF1.A110
PCIE_SLOT1_RXN15: CN2.A81(PERN15) GF1.A114
PCIE_SLOT1_RXP0: CN2.A16(PERP0) GF1.A52
PCIE_SLOT1_RXP1: CN2.A21(PERP1) GF1.A56
PCIE_SLOT1_RXP2: CN2.A25(PERP2) GF1.A60
PCIE_SLOT1_RXP3: CN2.A29(PERP3) GF1.A64
PCIE_SLOT1_RXP4: CN2.A35(PERP4) GF1.A68
PCIE_SLOT1_RXP5: CN2.A39(PERP5) GF1.A72
PCIE_SLOT1_RXP6: CN2.A43(PERP6) GF1.A76
PCIE_SLOT1_RXP7: CN2.A47(PERP7) GF1.A80
PCIE_SLOT1_RXP8: CN2.A52(PERP8) GF1.A85
PCIE_SLOT1_RXP9: CN2.A56(PERP9) GF1.A89
PCIE_SLOT1_RXP10: CN2.A60(PERP10) GF1.A93
PCIE_SLOT1_RXP11: CN2.A64(PERP11) GF1.A97
PCIE_SLOT1_RXP12: CN2.A68(PERP12) GF1.A101
PCIE_SLOT1_RXP13: CN2.A72(PERP13) GF1.A105
PCIE_SLOT1_RXP14: CN2.A76(PERP14) GF1.A109
PCIE_SLOT1_RXP15: CN2.A80(PERP15) GF1.A113
PCIE_SLOT1_TXN0: CN2.B15(PETN0) GF1.B51
PCIE_SLOT1_TXN1: CN2.B20(PETN1) GF1.B55
PCIE_SLOT1_TXN2: CN2.B24(PETN2) GF1.B59
PCIE_SLOT1_TXN3: CN2.B28(PETN3) GF1.B63
PCIE_SLOT1_TXN4: CN2.B34(PETN4) GF1.B67
PCIE_SLOT1_TXN5: CN2.B38(PETN5) GF1.B71
PCIE_SLOT1_TXN6: CN2.B42(PETN6) GF1.B75
PCIE_SLOT1_TXN7: CN2.B46(PETN7) GF1.B79
PCIE_SLOT1_TXN8: CN2.B51(PETN8) GF1.B84
PCIE_SLOT1_TXN9: CN2.B55(PETN9) GF1.B88
PCIE_SLOT1_TXN10: CN2.B59(PETN10) GF1.B92
PCIE_SLOT1_TXN11: CN2.B63(PETN11) GF1.B96
PCIE_SLOT1_TXN12: CN2.B67(PETN12) GF1.B100
PCIE_SLOT1_TXN13: CN2.B71(PETN13) GF1.B104
PCIE_SLOT1_TXN14: CN2.B75(PETN14) GF1.B108
PCIE_SLOT1_TXN15: CN2.B79(PETN15) GF1.B112
PCIE_SLOT1_TXP0: CN2.B14(PETP0) GF1.B50
PCIE_SLOT1_TXP1: CN2.B19(PETP1) GF1.B54
PCIE_SLOT1_TXP2: CN2.B23(PETP2) GF1.B58
PCIE_SLOT1_TXP3: CN2.B27(PETP3) GF1.B62
PCIE_SLOT1_TXP4: CN2.B33(PETP4) GF1.B66
PCIE_SLOT1_TXP5: CN2.B37(PETP5) GF1.B70
PCIE_SLOT1_TXP6: CN2.B41(PETP6) GF1.B74
PCIE_SLOT1_TXP7: CN2.B45(PETP7) GF1.B78
PCIE_SLOT1_TXP8: CN2.B50(PETP8) GF1.B83
PCIE_SLOT1_TXP9: CN2.B54(PETP9) GF1.B87
PCIE_SLOT1_TXP10: CN2.B58(PETP10) GF1.B91
PCIE_SLOT1_TXP11: CN2.B62(PETP11) GF1.B95
PCIE_SLOT1_TXP12: CN2.B66(PETP12) GF1.B99
PCIE_SLOT1_TXP13: CN2.B70(PETP13) GF1.B103
PCIE_SLOT1_TXP14: CN2.B74(PETP14) GF1.B107
PCIE_SLOT1_TXP15: CN2.B78(PETP15) GF1.B111
PCIE_SMCLK: GF1.B5 U10.1(SCL)
PCIE_SMCLK0: R14.2 RE1.2 U10.5(SC0)
PCIE_SMCLK1: R16.2 RE10.2 U10.8(SC1)
PCIE_SMDAT: GF1.B6 U10.2(SDA)
PCIE_SMDAT0: R13.2 RE7.2 U10.4(SD0)
PCIE_SMDAT1: R15.2 RE9.2 U10.7(SD1)
PCIE_WAKE_N: CN1.B11(WAKE#) CN2.B11(WAKE#) GF1.B11
PERST_N: CN1.A11(PERST#) CN2.A11(PERST#) R19.1 U9.4(Y)
PERST_N_1: R6.1 U8.4(Y)
PERST_N_1_R: R6.2 U9.2(B)
PERST_O_1_R: R3.2 R17.2 U8.1(A)
PERST_O_2_R: R4.2 R20.2 U9.1(A)
RESET_IN: C19.1 R1.2 R2.1 U1.3(VDD)
RESET_O_1: R3.1 U1.2(RESET#)
RESET_O_2: R4.1 U2.2(RESET#)
RESET_P3V3_IN: C23.1 R5.1 U2.3(VDD)
RSVD0: GF1.B30 TP6.1
RSVD1: GF1.A19 TP7.1
S0_PCIE_SMCLK: CN1.B5(SMCLK) RE1.1
S0_PCIE_SMDAT: CN1.B6(SMDAT) RE7.1
S0_SMB_ALERT_B12_N: CN1.B12(RSVD#B12) RE4.1
S0_SMB_CLK_A32: CN1.A32(RSVD#A32) RE2.2
S0_SMB_DAT_A33: CN1.A33(RSVD#A33) RE3.2
S1_PCIE_SMCLK: CN2.B5(SMCLK) RE10.1
S1_PCIE_SMDAT: CN2.B6(SMDAT) RE9.1
S1_SMB_ALERT_B12_N: CN2.B12(RSVD#B12) RE8.1
S1_SMB_CLK_A32: CN2.A32(RSVD#A32) RE5.2
S1_SMB_DAT_A33: CN2.A33(RSVD#A33) RE6.2
SLOT0_CONFIG: GF1.A50 R33.1
SLOT0_ID_0: CN1.A19(RSVD#A19) R7.1
SLOT0_ID_1: CN1.B30(RSVD#B30) R8.2
SLOT1_CONFIG: GF1.A83 R35.1
SLOT1_ID_0: CN2.A19(RSVD#A19) R9.2
SLOT1_ID_1: CN2.B30(RSVD#B30) R10.2

Not connected (* = marked no-connect by the designer): CN1 A5(JTAG2)* A6(JTAG3)* A7(JTAG4)* A8(JTAG5)* B9(JTAG1)* NP1* NP2*; CN2 A5(JTAG2)* A6(JTAG3)* A7(JTAG4)* A8(JTAG5)* A50(RSVD#A50)* B9(JTAG1)* B82(RSVD#B82)* NP1* NP2*

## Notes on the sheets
sheet 1
- HISTORY
- SA
  04/08
  1.  Connect CN1.G1 and CN1.G2 to GND
  2.  Add net "MB_PD_SLOT_PRSNT" and connect to A1 PRSNT pin of GF, CN1, and CN2
  3.  Change the order of PCIe CN1 Lane0~7 (Page 4)
  4.  NOPOP R32 & R34
  5.  Connect CN1/2.B31 to CN1/2.B17 for detecting a PCIe x1 card
  6.  Change net name P3V3 on GF to P3V3_MB and add a NOPOP 0 ohm between  P3V3 & P3V3_MB(Page 6)
  7.  Remove R11 & R12
  8.  Add 0.1uF decouple capacitor to VCC(Page 7)
  9.  Remove R18 & connect PCH_PLTRST_N to PERST_N
  10. Change R1 & R2 to tune voltage
  11. Change net name P3V3 of GF to P3V3_MB, and reserve a NOPOP 0-ohm between P3V3 and P3V3_MB
  04/13
  1. Change GF slot0 pcie lan0~7 order
  04/15
  1. Replace pcie smd type connectors with dip type
  04/29
  1. Remove power rail P3V3
  2. Remove 4pin power connector
  SB
  07/07
  1. Nopop TC1 and TC2
  MP-1
  04/13
  1. NOPOP U2,R5 and C23
sheet 2
- I2C-BUS MULTIPLEXER
sheet 3
- PCIE X24 RISER GF
- VIT=2.87 2.93 2.99
- Ra
- 0.5%
- AND GATE
- VCC + 0.5 V
  0.05mW
- Rb
- 0.5%
- AND GATE
sheet 4
- PCIE X16 RISER SLOT3
sheet 5
- PCIE X8 RISER SLOT2
sheet 6
- STACKUP
sheet 7
- BLOCK DIAGRAM
- PCIE x16 CONNECTOR (SLOT3)
- page. 5
- PCIE x8 CONNECTOR (SLOT2)
- page. 4
- PCA9540B
- page. 7
- PCIe x24 CONNECTOR ON THE MB
sheet 8
- Wiwynn Corporation
- Code Name: LEOPARD BW CHANNEL 2 SLOT PCIE RISER
  PCB No.:
  PCB P/N:
  Version: SA
  Date: 2016/07/04
  PCB Thinkness: 1.57mm
  Layer counter: 4 Layers
- WIWYNN CONFIDENTIAL
